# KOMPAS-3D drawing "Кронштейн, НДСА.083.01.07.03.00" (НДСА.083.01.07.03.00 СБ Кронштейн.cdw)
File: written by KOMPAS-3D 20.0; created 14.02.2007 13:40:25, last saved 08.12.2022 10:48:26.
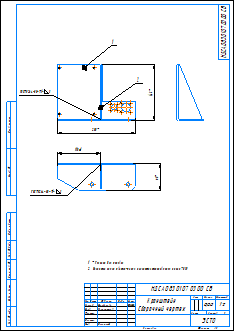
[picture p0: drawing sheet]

Sheet 1: A3, portrait

Document properties: Автор: Шубников; Организация: ЭСТО-Вакуум; Масса: 0.855389; PLM_CDWXDTO: <item xmlns="http://appius.ru/pdm" xmlns:xs="http://www.w3.org/2001/XMLSchema" xmlns:xsi="http://www.w3.org/2001/XMLSchema-instance" xsi:type="item">  <element xmlns:d2p1="http://v8.1c.ru/8.1/data/enterprise/current-config" xsi:type="d2p1:CatalogRef.aps_Элемен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; Полное имя файла: C:\Users\cherbakova\Desktop\Виноград\Новая папка (3)\НДСА.083.01.07.03.00 СБ Кронштейн.cdw

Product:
- Part/product: Кронштейн  | designation НДСА.083.01.07.03.00
    Масса: 0.855389

Title block, sheet 1: Наименование: Кронштейн / Сборочный чертеж; Масса: 0,86; scale: 1:2; Количество листов документа: 1; organisation: ЭСТО; Форматы листов документа: A3; stored path: E:\WorkPDM\Шубников А.В\7874fb5b-6de3-432a-b1f0-0303b466e214\УКРД.787.01.12.10.00 СБ Кронштейн.cdw; Разработал: Щербакова; Проверил: Горностаев; Утвердил: Белецкий; Разработал, date: 08.12.2022

Views: Проекционный вид 7, Проекционный вид 8
Referenced files in C:\Users\cherbakova\Desktop\Виноград\Новая папка (3)\: НДСА.083.01.07.03.01 Лист.m3d, НДСА.083.01.07.03.02 Косынка.m3d, НДСА.083.01.07.03.00 Кронштейн.a3d
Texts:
  ГОСТ5264-80-Т1- 3
  НДСА.083.01.07.03.00
  Лист
  НДСА.083.01.07.03.01
  НДСА.083.01.07.03.01 Лист
  Косынка
  НДСА.083.01.07.03.02
  НДСА.083.01.07.03.02 Косынка
  НДСА.083.01.07.03.00 Кронштейн
Dimensions and other numbers on the sheet: 68; 110±1; 4; 1:2; 1; 0,86; 08.12.2022

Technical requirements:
  * Размеры для справок.
  Покрытие эмаль светло-серая, мелкостуктурированная, номер 7035.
